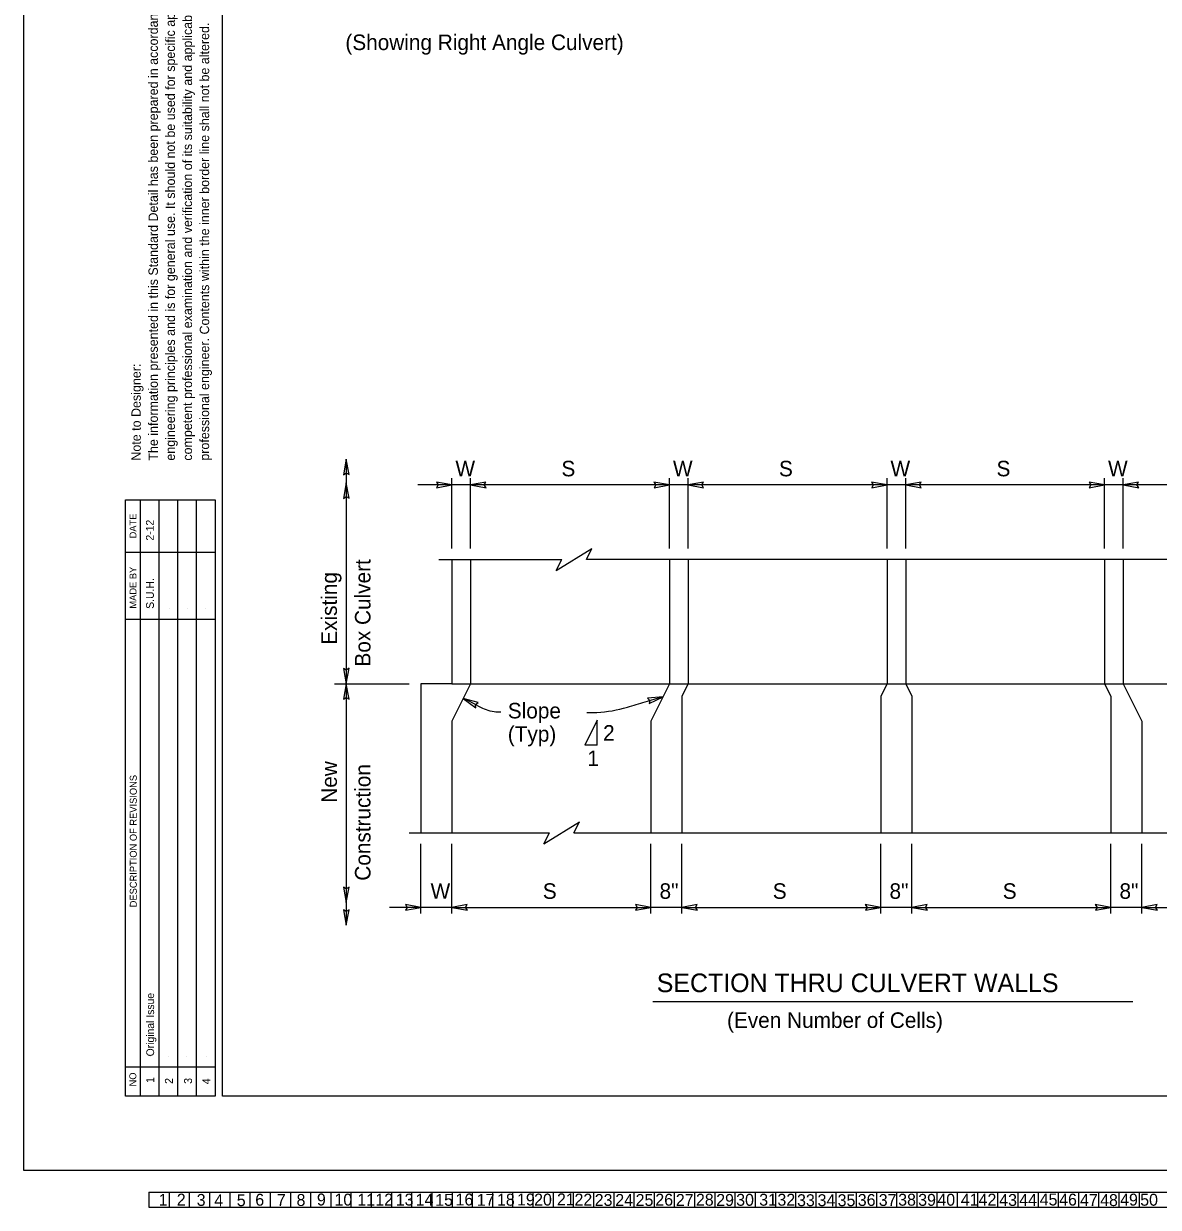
# Model space of a CAD drawing. Extents: x -0.08 to 2.83, y -0.03 to 1.92.
# Drawn here: x 0 to 0.951, y -0.031 to 0.961 of the extents above; entities that cross this region are included whole.
import ezdxf

# ---------------------------------------------------------------- set-up
doc = ezdxf.new("R2010")
doc.units = 0
for name, color, linetype in [('1', 7, 'Continuous'), ('10', 7, 'Continuous'), ('11', 7, 'Continuous'), ('12', 7, 'Continuous'), ('13', 7, 'Continuous'), ('14', 7, 'Continuous'), ('15', 7, 'Continuous'), ('16', 7, 'Continuous'), ('17', 7, 'Continuous'), ('18', 7, 'Continuous'), ('19', 7, 'Continuous'), ('2', 7, 'Continuous'), ('20', 7, 'Continuous'), ('21', 7, 'Continuous'), ('22', 7, 'Continuous'), ('23', 7, 'Continuous'), ('24', 7, 'Continuous'), ('25', 7, 'Continuous'), ('26', 7, 'Continuous'), ('27', 7, 'Continuous'), ('28', 7, 'Continuous'), ('29', 7, 'Continuous'), ('3', 7, 'Continuous'), ('30', 7, 'Continuous'), ('31', 7, 'Continuous'), ('32', 7, 'Continuous'), ('33', 7, 'Continuous'), ('34', 7, 'Continuous'), ('35', 7, 'Continuous'), ('36', 7, 'Continuous'), ('37', 7, 'Continuous'), ('38', 7, 'Continuous'), ('39', 7, 'Continuous'), ('4', 7, 'Continuous'), ('40', 7, 'Continuous'), ('41', 7, 'Continuous'), ('42', 7, 'Continuous'), ('43', 7, 'Continuous'), ('44', 7, 'Continuous'), ('45', 7, 'Continuous'), ('46', 7, 'Continuous'), ('47', 7, 'Continuous'), ('48', 7, 'Continuous'), ('49', 7, 'Continuous'), ('5', 7, 'Continuous'), ('50', 7, 'Continuous'), ('54', 7, 'Continuous'), ('55', 7, 'Continuous'), ('57', 7, 'Continuous'), ('6', 7, 'Continuous'), ('62', 7, 'Continuous'), ('63', 7, 'Continuous'), ('7', 7, 'Continuous'), ('8', 7, 'Continuous'), ('9', 7, 'Continuous')]:
    doc.layers.add(name, color=color, linetype=linetype)

msp = doc.modelspace()

# ---------------------------------------------------------------- linework, layer by layer
at = {"layer": '50'}
for p, q in [((0.35889, 0.5123), (0.35889, 0.40813)), ((0.37451, 0.5123), (0.37451, 0.40813)), ((0.54118, 0.5123), (0.54118, 0.40813)), ((0.55681, 0.5123), (0.55681, 0.40813)), ((0.72347, 0.5123), (0.72347, 0.40813)), ((0.7391, 0.5123), (0.7391, 0.40813)), ((0.90576, 0.5123), (0.90576, 0.40813)), ((0.92139, 0.5123), (0.92139, 0.40813)), ((0.33285, 0.40813), (0.33285, 0.28313)), ((0.35889, 0.40813), (0.33285, 0.40813)), ((0.35889, 0.40813), (1.10368, 0.40813)), ((0.37451, 0.40813), (0.35889, 0.37688)), ((0.54118, 0.40813), (0.52556, 0.37688)), ((0.55681, 0.40813), (0.5516, 0.39772)), ((0.72347, 0.40813), (0.71826, 0.39772)), ((0.7391, 0.40813), (0.74431, 0.39772)), ((0.90576, 0.40813), (0.91097, 0.39772)), ((0.92139, 0.40813), (0.93701, 0.37688)), ((0.5516, 0.39772), (0.5516, 0.28313)), ((0.71826, 0.39772), (0.71826, 0.28313)), ((0.74431, 0.39772), (0.74431, 0.28313)), ((0.91097, 0.39772), (0.91097, 0.28313)), ((0.35889, 0.37688), (0.35889, 0.28313)), ((0.52556, 0.37688), (0.52556, 0.28313)), ((0.93701, 0.37688), (0.93701, 0.28313))]:
    msp.add_line(p, q, dxfattribs=at)
at = {"layer": '54'}
for points in [[(0.27035, 0.59632), (0.26797, 0.58333), (0.27035, 0.58484), (0.27275, 0.58348)], [(0.27035, 0.57656), (0.26797, 0.56357), (0.27035, 0.56508), (0.27275, 0.56372)], [(0.35889, 0.5748), (0.3459, 0.57717), (0.34741, 0.5748), (0.34605, 0.5724)], [(0.37451, 0.5748), (0.38751, 0.57242), (0.386, 0.5748), (0.38736, 0.5772)], [(0.54118, 0.5748), (0.52819, 0.57717), (0.5297, 0.5748), (0.52834, 0.5724)], [(0.55681, 0.5748), (0.5698, 0.57242), (0.56829, 0.5748), (0.56965, 0.5772)], [(0.72347, 0.5748), (0.71048, 0.57717), (0.71199, 0.5748), (0.71063, 0.5724)], [(0.7391, 0.5748), (0.75209, 0.57242), (0.75058, 0.5748), (0.75194, 0.5772)], [(0.90576, 0.5748), (0.89277, 0.57717), (0.89428, 0.5748), (0.89292, 0.5724)], [(0.92139, 0.5748), (0.93438, 0.57242), (0.93287, 0.5748), (0.93423, 0.5772)], [(0.27035, 0.40813), (0.27272, 0.42112), (0.27035, 0.41962), (0.26795, 0.42097)], [(0.27035, 0.40813), (0.26797, 0.39514), (0.27035, 0.39665), (0.27275, 0.39529)], [(0.53577, 0.39732), (0.52262, 0.39609), (0.52472, 0.39421), (0.52406, 0.39154)], [(0.3684, 0.39589), (0.37898, 0.388), (0.37868, 0.39079), (0.38097, 0.39234)], [(0.27035, 0.22475), (0.27272, 0.23774), (0.27035, 0.23623), (0.26795, 0.23759)], [(0.27035, 0.20575), (0.27272, 0.21874), (0.27035, 0.21723), (0.26795, 0.21859)], [(0.33285, 0.22063), (0.31986, 0.22301), (0.32136, 0.22063), (0.32001, 0.21823)], [(0.35889, 0.22063), (0.37188, 0.21826), (0.37037, 0.22063), (0.37173, 0.22303)], [(0.52556, 0.22063), (0.51256, 0.22301), (0.51407, 0.22063), (0.51271, 0.21823)], [(0.5516, 0.22063), (0.56459, 0.21826), (0.56308, 0.22063), (0.56444, 0.22303)], [(0.71826, 0.22063), (0.70527, 0.22301), (0.70678, 0.22063), (0.70542, 0.21823)], [(0.74431, 0.22063), (0.7573, 0.21826), (0.75579, 0.22063), (0.75715, 0.22303)], [(0.91097, 0.22063), (0.89798, 0.22301), (0.89949, 0.22063), (0.89813, 0.21823)], [(0.93701, 0.22063), (0.95001, 0.21826), (0.9485, 0.22063), (0.94986, 0.22303)]]:
    msp.add_lwpolyline(points, close=True, dxfattribs=at)
at = {"layer": '55'}
for p, q in [((0.27035, 0.59632), (0.27035, 0.40813)), ((0.35889, 0.52155), (0.35889, 0.58036)), ((0.37451, 0.52155), (0.37451, 0.58036)), ((0.54118, 0.52155), (0.54118, 0.58036)), ((0.55681, 0.52155), (0.55681, 0.58036)), ((0.72347, 0.52155), (0.72347, 0.58036)), ((0.7391, 0.52155), (0.7391, 0.58036)), ((0.90576, 0.52155), (0.90576, 0.58036)), ((0.92139, 0.52155), (0.92139, 0.58036)), ((0.35889, 0.5748), (0.33042, 0.5748)), ((0.37451, 0.5748), (0.35889, 0.5748)), ((0.54118, 0.5748), (0.37451, 0.5748)), ((0.55681, 0.5748), (0.54118, 0.5748)), ((0.72347, 0.5748), (0.55681, 0.5748)), ((0.7391, 0.5748), (0.72347, 0.5748)), ((0.90576, 0.5748), (0.7391, 0.5748)), ((0.92139, 0.5748), (0.90576, 0.5748)), ((1.08806, 0.5748), (0.92139, 0.5748)), ((0.44631, 0.50305), (0.47615, 0.52155)), ((0.47153, 0.5123), (0.47615, 0.52155)), ((0.34802, 0.5123), (0.45094, 0.5123)), ((0.44631, 0.50305), (0.45094, 0.5123)), ((0.99781, 0.5123), (0.47153, 0.5123)), ((0.26042, 0.40813), (0.32299, 0.40813)), ((0.27035, 0.40813), (0.27035, 0.20575)), ((0.48061, 0.37762), (0.47019, 0.35679)), ((0.48061, 0.35679), (0.48061, 0.37762)), ((0.48061, 0.35679), (0.47019, 0.35679)), ((0.4359, 0.27389), (0.46573, 0.29238)), ((0.46111, 0.28313), (0.46573, 0.29238)), ((0.32299, 0.28313), (0.44052, 0.28313)), ((0.4359, 0.27389), (0.44052, 0.28313)), ((0.46111, 0.28313), (1.00823, 0.28313)), ((0.33285, 0.21563), (0.33285, 0.27389)), ((0.35889, 0.21563), (0.35889, 0.27389)), ((0.52556, 0.21563), (0.52556, 0.27389)), ((0.5516, 0.21563), (0.5516, 0.27389)), ((0.71826, 0.21563), (0.71826, 0.27389)), ((0.74431, 0.21563), (0.74431, 0.27389)), ((0.91097, 0.21563), (0.91097, 0.27389)), ((0.93701, 0.21563), (0.93701, 0.27389)), ((0.33285, 0.22063), (0.30655, 0.22063)), ((0.35889, 0.22063), (0.33285, 0.22063)), ((0.35889, 0.22063), (0.52556, 0.22063)), ((0.5516, 0.22063), (0.52556, 0.22063)), ((0.5516, 0.22063), (0.71826, 0.22063)), ((0.74431, 0.22063), (0.71826, 0.22063)), ((0.74431, 0.22063), (0.91097, 0.22063)), ((0.93701, 0.22063), (0.91097, 0.22063)), ((0.93701, 0.22063), (1.10368, 0.22063))]:
    msp.add_line(p, q, dxfattribs=at)
for points in [[(0.4718, 0.38419), (0.48032, 0.38419), (0.50589, 0.38852), (0.52081, 0.39311), (0.53577, 0.39732)], [(0.39998, 0.38445), (0.39578, 0.38445), (0.38315, 0.38822), (0.37579, 0.39223), (0.3684, 0.39589)]]:
    msp.add_spline(points, degree=3, dxfattribs=at)
at = {"layer": '57'}
msp.add_line((0.52725, 0.14182), (0.92957, 0.14182), dxfattribs=at)
at = {"layer": '62'}
for p, q in [((0.10585, 0.47101), (0.10585, 0.47101)), ((0.12188, 0.47101), (0.12188, 0.47101)), ((0.13719, 0.47101), (0.13719, 0.47101)), ((0.15252, 0.47101), (0.15252, 0.47101)), ((0.10603, 0.09579), (0.10603, 0.09579)), ((0.121, 0.09544), (0.121, 0.09544)), ((0.13668, 0.09544), (0.13668, 0.09544)), ((0.15304, 0.09579), (0.15304, 0.09579)), ((0.10494, -0.01804), (1.17174, -0.01804)), ((0.10494, -0.01804), (0.10494, -0.03074)), ((0.12188, -0.01804), (0.12188, -0.03074)), ((0.13881, -0.01804), (0.13881, -0.03074)), ((0.15574, -0.01804), (0.15574, -0.03074)), ((0.17267, -0.01804), (0.17267, -0.03074)), ((0.18961, -0.01804), (0.18961, -0.03074)), ((0.20654, -0.01804), (0.20654, -0.03074)), ((0.22348, -0.01804), (0.22348, -0.03074)), ((0.24041, -0.01804), (0.24041, -0.03074)), ((0.25734, -0.01804), (0.25734, -0.03074)), ((0.27427, -0.01804), (0.27427, -0.03074)), ((0.29121, -0.01804), (0.29121, -0.03074)), ((0.30814, -0.01804), (0.30814, -0.03074)), ((0.32508, -0.01804), (0.32508, -0.03074)), ((0.34201, -0.01804), (0.34201, -0.03074)), ((0.35894, -0.01804), (0.35894, -0.03074)), ((0.37588, -0.01804), (0.37588, -0.03074)), ((0.39281, -0.01804), (0.39281, -0.03074)), ((0.40974, -0.01804), (0.40974, -0.03074)), ((0.42668, -0.01804), (0.42668, -0.03074)), ((0.44361, -0.01804), (0.44361, -0.03074)), ((0.46054, -0.01804), (0.46054, -0.03074)), ((0.47748, -0.01804), (0.47748, -0.03074)), ((0.49441, -0.01804), (0.49441, -0.03074)), ((0.51134, -0.01804), (0.51134, -0.03074)), ((0.52828, -0.01804), (0.52828, -0.03074)), ((0.54521, -0.01804), (0.54521, -0.03074)), ((0.56214, -0.01804), (0.56214, -0.03074)), ((0.57908, -0.01804), (0.57908, -0.03074)), ((0.59601, -0.01804), (0.59601, -0.03074)), ((0.61294, -0.01804), (0.61294, -0.03074)), ((0.62988, -0.01804), (0.62988, -0.03074)), ((0.64681, -0.01804), (0.64681, -0.03074)), ((0.66374, -0.01804), (0.66374, -0.03074)), ((0.68068, -0.01804), (0.68068, -0.03074)), ((0.69761, -0.01804), (0.69761, -0.03074)), ((0.71454, -0.01804), (0.71454, -0.03074)), ((0.73147, -0.01804), (0.73147, -0.03074)), ((0.74841, -0.01804), (0.74841, -0.03074)), ((0.76534, -0.01804), (0.76534, -0.03074)), ((0.78228, -0.01804), (0.78228, -0.03074)), ((0.79921, -0.01804), (0.79921, -0.03074)), ((0.81614, -0.01804), (0.81614, -0.03074)), ((0.83308, -0.01804), (0.83308, -0.03074)), ((0.85001, -0.01804), (0.85001, -0.03074)), ((0.86694, -0.01804), (0.86694, -0.03074)), ((0.88388, -0.01804), (0.88388, -0.03074)), ((0.90081, -0.01804), (0.90081, -0.03074)), ((0.91774, -0.01804), (0.91774, -0.03074)), ((0.93468, -0.01804), (0.93468, -0.03074)), ((0.10494, -0.03074), (1.17174, -0.03074))]:
    msp.add_line(p, q, dxfattribs=at)
at = {"layer": '63'}
for p, q in [((0, 0), (0, 1.83333)), ((0.08543, 0.06244), (0.08543, 0.56244)), ((0.08543, 0.56244), (0.16043, 0.56244)), ((0.09792, 0.06244), (0.09792, 0.56244)), ((0.11353, 0.06259), (0.11353, 0.56244)), ((0.12914, 0.06275), (0.12914, 0.56244)), ((0.14474, 0.0629), (0.14474, 0.56244)), ((0.16043, 0.56244), (0.16043, 0.06244)), ((0.08543, 0.51859), (0.16043, 0.51859)), ((0.08543, 0.46218), (0.16043, 0.46218)), ((0.08543, 0.08707), (0.16043, 0.08707)), ((0.16043, 0.06244), (0.08543, 0.06244)), ((2.83333, 0), (0, 0))]:
    msp.add_line(p, q, dxfattribs=at)
msp.add_lwpolyline([(0.16668, 0.06244), (0.16668, 1.77077), (2.72918, 1.77077), (2.72918, 0.10411), (2.56251, 0.10411), (2.56251, 0.14578), (2.07387, 0.14578), (2.07387, 0.06244)], close=True, dxfattribs=at)

# ---------------------------------------------------------------- texts
at = {"layer": '1'}
msp.add_text('1', height=0.01, rotation=360, dxfattribs=at).set_placement((0.11316, -0.02944))
at = {"layer": '10'}
msp.add_text('10', height=0.01, rotation=360, dxfattribs=at).set_placement((0.26046, -0.02928))
at = {"layer": '11'}
msp.add_text('11', height=0.01, rotation=360, dxfattribs=at).set_placement((0.2796, -0.02937))
at = {"layer": '12'}
msp.add_text('12', height=0.01, rotation=360, dxfattribs=at).set_placement((0.29469, -0.02925))
at = {"layer": '13'}
msp.add_text('13', height=0.01, rotation=360, dxfattribs=at).set_placement((0.31181, -0.02928))
at = {"layer": '14'}
msp.add_text('14', height=0.01, rotation=360, dxfattribs=at).set_placement((0.32844, -0.02939))
at = {"layer": '15'}
msp.add_text('15', height=0.01, rotation=360, dxfattribs=at).set_placement((0.34488, -0.02946))
at = {"layer": '16'}
msp.add_text('16', height=0.01, rotation=360, dxfattribs=at).set_placement((0.3619, -0.02918))
at = {"layer": '17'}
msp.add_text('17', height=0.01, rotation=360, dxfattribs=at).set_placement((0.3797, -0.02946))
at = {"layer": '18'}
msp.add_text('18', height=0.01, rotation=360, dxfattribs=at).set_placement((0.39663, -0.02938))
at = {"layer": '19'}
msp.add_text('19', height=0.01, rotation=360, dxfattribs=at).set_placement((0.4134, -0.02918))
at = {"layer": '2'}
msp.add_text('2', height=0.01, rotation=360, dxfattribs=at).set_placement((0.12828, -0.02928))
at = {"layer": '20'}
msp.add_text('20', height=0.01, rotation=360, dxfattribs=at).set_placement((0.42774, -0.02926))
at = {"layer": '21'}
msp.add_text('21', height=0.01, rotation=360, dxfattribs=at).set_placement((0.44688, -0.02909))
at = {"layer": '22'}
msp.add_text('22', height=0.01, rotation=360, dxfattribs=at).set_placement((0.46158, -0.02929))
at = {"layer": '23'}
msp.add_text('23', height=0.01, rotation=360, dxfattribs=at).set_placement((0.47852, -0.02958))
at = {"layer": '24'}
msp.add_text('24', height=0.01, rotation=360, dxfattribs=at).set_placement((0.49576, -0.02958))
at = {"layer": '25'}
msp.add_text('25', height=0.01, rotation=360, dxfattribs=at).set_placement((0.51281, -0.02958))
at = {"layer": '26'}
msp.add_text('26', height=0.01, rotation=360, dxfattribs=at).set_placement((0.52931, -0.02936))
at = {"layer": '27'}
msp.add_text('27', height=0.01, rotation=360, dxfattribs=at).set_placement((0.54648, -0.02958))
at = {"layer": '28'}
msp.add_text('28', height=0.01, rotation=360, dxfattribs=at).set_placement((0.56333, -0.02938))
at = {"layer": '29'}
msp.add_text('29', height=0.01, rotation=360, dxfattribs=at).set_placement((0.58032, -0.02956))
at = {"layer": '3'}
msp.add_text('3', height=0.01, rotation=360, dxfattribs=at).set_placement((0.145, -0.02955))
at = {"layer": '30'}
msp.add_text('30', height=0.01, rotation=360, dxfattribs=at).set_placement((0.59706, -0.02946))
at = {"layer": '31'}
msp.add_text('31', height=0.01, rotation=360, dxfattribs=at).set_placement((0.61636, -0.02938))
at = {"layer": '32'}
msp.add_text('32', height=0.01, rotation=360, dxfattribs=at).set_placement((0.63163, -0.02938))
at = {"layer": '33'}
msp.add_text('33', height=0.01, rotation=360, dxfattribs=at).set_placement((0.64808, -0.02978))
at = {"layer": '34'}
msp.add_text('34', height=0.01, rotation=360, dxfattribs=at).set_placement((0.66527, -0.02978))
at = {"layer": '35'}
msp.add_text('35', height=0.01, rotation=360, dxfattribs=at).set_placement((0.68209, -0.02978))
at = {"layer": '36'}
msp.add_text('36', height=0.01, rotation=360, dxfattribs=at).set_placement((0.69895, -0.02958))
at = {"layer": '37'}
msp.add_text('37', height=0.01, rotation=360, dxfattribs=at).set_placement((0.71654, -0.02958))
at = {"layer": '38'}
msp.add_text('38', height=0.01, rotation=360, dxfattribs=at).set_placement((0.73281, -0.02938))
at = {"layer": '39'}
msp.add_text('39', height=0.01, rotation=360, dxfattribs=at).set_placement((0.74958, -0.0295))
at = {"layer": '4'}
msp.add_text('4', height=0.01, rotation=360, dxfattribs=at).set_placement((0.15973, -0.02984))
at = {"layer": '40'}
msp.add_text('40', height=0.01, rotation=360, dxfattribs=at).set_placement((0.76566, -0.02938))
at = {"layer": '41'}
msp.add_text('41', height=0.01, rotation=360, dxfattribs=at).set_placement((0.78528, -0.02938))
at = {"layer": '42'}
msp.add_text('42', height=0.01, rotation=360, dxfattribs=at).set_placement((0.8002, -0.0293))
at = {"layer": '43'}
msp.add_text('43', height=0.01, rotation=360, dxfattribs=at).set_placement((0.8175, -0.02958))
at = {"layer": '44'}
msp.add_text('44', height=0.01, rotation=360, dxfattribs=at).set_placement((0.83425, -0.02949))
at = {"layer": '45'}
msp.add_text('45', height=0.01, rotation=360, dxfattribs=at).set_placement((0.85139, -0.02918))
at = {"layer": '46'}
msp.add_text('46', height=0.01, rotation=360, dxfattribs=at).set_placement((0.8677, -0.02929))
at = {"layer": '47'}
msp.add_text('47', height=0.01, rotation=360, dxfattribs=at).set_placement((0.8852, -0.02958))
at = {"layer": '48'}
msp.add_text('48', height=0.01, rotation=360, dxfattribs=at).set_placement((0.90205, -0.02969))
at = {"layer": '49'}
msp.add_text('49', height=0.01, rotation=360, dxfattribs=at).set_placement((0.91882, -0.02929))
at = {"layer": '5'}
msp.add_text('5', height=0.01, rotation=360, dxfattribs=at).set_placement((0.17858, -0.02977))
at = {"layer": '50'}
msp.add_text('50', height=0.01, rotation=360, dxfattribs=at).set_placement((0.93563, -0.02938))
at = {"layer": '55'}
for s, height, p in [('The information presented in this Standard Detail has been prepared in accordance with recognized', 0.0078167, (0.11243, 0.59517)), ('engineering principles and is for general use. It should not be used for specific application without', 0.00781665, (0.12676, 0.59517)), ('competent professional examination and verification of its suitability and applicability by a licensed', 0.00781665, (0.14108, 0.59517)), ('professional engineer. Contents within the inner border line shall not be altered.', 0.0078167, (0.15541, 0.59517)), ('Note to Designer:', 0.0078167, (0.09811, 0.59517))]:
    msp.add_text(s, height=height, rotation=90, dxfattribs=at).set_placement(p)
at = {"layer": '57'}
for s, height, p in [('(Showing Right Angle Culvert)', 0.0130208, (0.26958, 0.93936)), ('W', 0.01302, (0.36181, 0.58203)), ('S', 0.01302, (0.45064, 0.58203)), ('W', 0.01302, (0.5441, 0.58203)), ('S', 0.01302, (0.63293, 0.58203)), ('W', 0.01302, (0.72639, 0.58203)), ('S', 0.01302, (0.81522, 0.58203)), ('W', 0.01302, (0.90868, 0.58203)), ('Slope', 0.013021, (0.40568, 0.3791)), ('(Typ)', 0.013021, (0.40568, 0.35957)), ('2', 0.01302, (0.48554, 0.36047)), ('1', 0.01302, (0.47239, 0.33916)), ('W', 0.01302, (0.34098, 0.22786)), ('S', 0.01302, (0.43502, 0.22786)), ('8"', 0.013021, (0.53286, 0.22786)), ('S', 0.01302, (0.62772, 0.22786)), ('8"', 0.013021, (0.72557, 0.22786)), ('S', 0.01302, (0.82043, 0.22786)), ('8"', 0.013021, (0.91828, 0.22786)), ('SECTION THRU CULVERT WALLS', 0.015625, (0.5305, 0.14963)), ('(Even Number of Cells)', 0.0130208, (0.58939, 0.11967))]:
    msp.add_text(s, height=height, dxfattribs=at).set_placement(p)
for s, height, p in [('Box Culvert', 0.0130208, (0.29062, 0.42258)), ('Existing', 0.013021, (0.26249, 0.44082)), ('New', 0.013021, (0.26249, 0.30841)), ('Construction', 0.0130208, (0.29062, 0.24305))]:
    msp.add_text(s, height=height, rotation=90, dxfattribs=at).set_placement(p)
at = {"layer": '6'}
msp.add_text('6', height=0.01, rotation=360, dxfattribs=at).set_placement((0.19409, -0.02938))
at = {"layer": '62'}
for s, height, p in [(' 2-12', 0.006508, (0.10896, 0.52578)), ('S.U.H.  ', 0.006508, (0.1091, 0.47101)), ('Original Issue                                                   ', 0.0065084, (0.10928, 0.09579))]:
    msp.add_text(s, height=height, rotation=90, dxfattribs=at).set_placement(p)
at = {"layer": '63'}
for s, height, p in [('DATE', 0.005833, (0.09454, 0.53)), ('MADE BY', 0.005833, (0.09454, 0.47113)), ('DESCRIPTION OF REVISIONS', 0.0058333, (0.09477, 0.22076)), ('NO', 0.005833, (0.09439, 0.07059)), ('1', 0.00667, (0.10936, 0.0735)), ('2', 0.00667, (0.12503, 0.07272)), ('3', 0.00667, (0.14105, 0.07272)), ('4', 0.00667, (0.15638, 0.07237))]:
    msp.add_text(s, height=height, rotation=90, dxfattribs=at).set_placement(p)
at = {"layer": '7'}
msp.add_text('7', height=0.01, rotation=360, dxfattribs=at).set_placement((0.21211, -0.02964))
at = {"layer": '8'}
msp.add_text('8', height=0.01, rotation=360, dxfattribs=at).set_placement((0.22865, -0.02958))
at = {"layer": '9'}
msp.add_text('9', height=0.01, rotation=360, dxfattribs=at).set_placement((0.24573, -0.02921))

doc.saveas('drawing.dxf')
